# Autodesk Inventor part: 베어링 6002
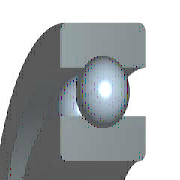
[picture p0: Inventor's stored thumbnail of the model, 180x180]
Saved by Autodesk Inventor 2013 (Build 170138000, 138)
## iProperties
Created: 2012-02
Part Number: 베어링 6002
Material: 강철, 연강
Description: 깊은 그루브 볼 베어링
Document SubType Name: Modeling
Standard: KS B 2023
Designer: mduedu
Standards Organization: KS
Language: ko-KR
Size Designation: 6002 - 15 x 32 x 9
Categories: <MemberInstance><Categories><Category DisplayName="샤프트 부품" InternalName="7f7aeb1f-a693-4053-b835-cee3144e0d98" Mnemonic="SHFT"><Category DisplayName="베어링" Inter
Density: 1 g/cm^3
IsCustomPart: 1
Author: mduedu
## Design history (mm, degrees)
sketch "스케치" dims "d0" = 4.42 (= -0.26 x WD + 0.26 x BD)
  geometry: L1 (2.29, 11.75)-(6.71, 11.75); L2 (4.5, 11.75)-(4.5, 9.54); L3 (4.5, 11.75)-(4.5, 13.96); L4 (2.858, 10.271)-(0, 10.271); L5 (0, 7.5)-(9, 7.5); L6 (2.858, 13.229)-(0, 13.229); L7 (0, 16)-(9, 16); L8 (9, 7.5)-(9, 10.271); L9 (6.142, 10.271)-(9, 10.271); L10 (6.142, 13.229)-(9, 13.229); L11 (9, 16)-(9, 13.229); L12 (-1.4, 0)-(8.4, 0) reference; L13 (0, -0.3)-(0, 5.3) reference
  constraints: 22 end point, 4 point on line, 2 collinear, 2 perpendicular, 2 symmetric about line, 1 midpoint, 1 parallel, 14 other
  dimensions: "d9" = 15 diameter of L5 L12 (= WD); "d11" = 32 diameter of L7 L12 (= BD); "d12" = 9 distance between parallel lines of L8 L13 (= KB); "d13" = 20.542 diameter of L9 L12 (= 0.326 x BD + 0.674 x WD)
revolve "본체" stored, may be unused: angle "d6" = 90 deg
revolve "볼" stored, may be unused: angle "d7" = 90 deg
pattern_circular "IDS_ARRAYBALL[SIMPL:T]" dims angle "d3" = 360 deg
body "Solid1"
fillet "모깎기1" dims "d1" = 0.3 (= KRS)
other parameters: "WD" = 15 [user parameter; used in 5 equation terms], "BD" = 32 [user parameter; used in 5 equation terms], "KB" = 9 [user parameter; used in 1 equation term], "KRS" = 0.3 [user parameter; used in 1 equation term], "d4" = 0, "d5" = 0, "d8" = 0, "d14" = 0, "d15" = 0, "BBA" = 0 [user parameter], "BC0" = 2850000 [user parameter], "BC" = 5590000 [user parameter], "BR" = 16 (= 0.5 x BD) [user parameter], "WR" = 7.5 (= 0.5 x WD) [user parameter]
